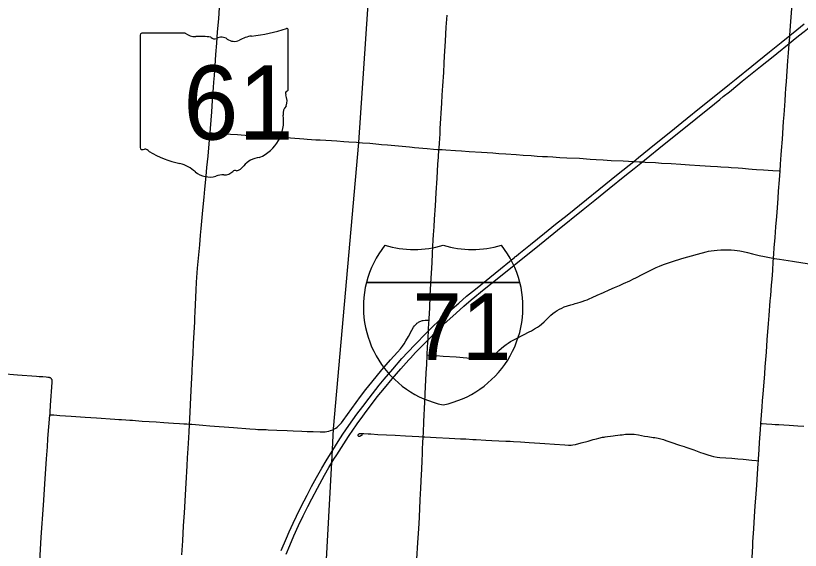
# Model space of a CAD drawing. Extents: x 9078 to 9739, y 4248 to 4966.
# Drawn here: x 9374.4 to 9448.2, y 4419.9 to 4470.1 of the extents above; entities that cross this region are included whole.
import ezdxf

# ---------------------------------------------------------------- set-up
doc = ezdxf.new("R2010")
doc.units = 0
for name, color, linetype in [('GM_X_County_Road', 7, 'Continuous'), ('GM_X_Interstate_Route', 7, 'Continuous'), ('GM_X_Interstate_Shield', 7, 'Continuous'), ('GM_X_State_Route', 7, 'Continuous'), ('GM_X_State_Shield', 7, 'Continuous'), ('GM_X_Township', 7, 'Continuous'), ('GM_X_Township_Road', 7, 'Continuous')]:
    doc.layers.add(name, color=color, linetype=linetype)

msp = doc.modelspace()

# ---------------------------------------------------------------- linework, layer by layer
at = {"layer": 'GM_X_County_Road'}
for points in [[(9446.815, 4462.765), (9446.846, 4463.245), (9446.893, 4463.899), (9446.967, 4464.88), (9447.035, 4465.861), (9447.094, 4466.597), (9447.155, 4467.414), (9447.16, 4467.488), (9447.203, 4468.076), (9447.214, 4468.229), (9447.278, 4469.132), (9447.369, 4470.358), (9447.496, 4471.993), (9447.569, 4472.974), (9447.574, 4473.033)], [(9414.23, 4457.523), (9414.239, 4457.66), (9414.267, 4458.106), (9414.329, 4459.006), (9414.358, 4459.498), (9414.495, 4461.873), (9414.545, 4462.61), (9414.602, 4463.511), (9414.675, 4464.739), (9414.726, 4465.641), (9414.76, 4466.296), (9414.843, 4467.688), (9414.918, 4468.998), (9414.99, 4470.144)], [(9446.305, 4455.497), (9446.352, 4456.128), (9446.414, 4457.027), (9446.44, 4457.436), (9446.514, 4458.5), (9446.632, 4460.136), (9446.675, 4460.79), (9446.771, 4462.099), (9446.815, 4462.765)], [(9413.296, 4441.491), (9413.306, 4441.652), (9413.359, 4442.626), (9413.418, 4443.774), (9413.481, 4444.921), (9413.535, 4445.904), (9413.589, 4446.887), (9413.635, 4447.789), (9413.693, 4449.018), (9413.723, 4449.509), (9413.768, 4450.246), (9413.813, 4450.983), (9413.89, 4452.212), (9413.969, 4453.44), (9414.054, 4454.832), (9414.095, 4455.487), (9414.138, 4456.142), (9414.182, 4456.796), (9414.23, 4457.523)], [(9445.685, 4447.299), (9445.715, 4447.72), (9445.759, 4448.279), (9445.831, 4449.26), (9445.906, 4450.241), (9445.982, 4451.222), (9446.048, 4452.04), (9446.111, 4452.939), (9446.158, 4453.594), (9446.242, 4454.656), (9446.305, 4455.497)], [(9444.5, 4431.771), (9444.611, 4433.337), (9444.657, 4433.909), (9444.71, 4434.563), (9444.774, 4435.298), (9444.857, 4436.442), (9444.905, 4437.096), (9445.012, 4438.486), (9445.093, 4439.631), (9445.217, 4441.184), (9445.277, 4441.919), (9445.383, 4443.309), (9445.421, 4443.799), (9445.501, 4444.779), (9445.547, 4445.351), (9445.611, 4446.167), (9445.66, 4446.972), (9445.685, 4447.299)], [(9413.282, 4441.228), (9413.296, 4441.491)], [(9413.166, 4438.988), (9413.167, 4439.015), (9413.201, 4439.652), (9413.212, 4439.867), (9413.241, 4440.471), (9413.248, 4440.614), (9413.282, 4441.228)], [(9413.127, 4438.224), (9413.166, 4438.988)], [(9413.033, 4436.461), (9413.038, 4436.564), (9413.08, 4437.301), (9413.127, 4438.224)], [(9412.744, 4430.538), (9412.763, 4430.909), (9412.817, 4431.975), (9412.906, 4433.777), (9412.971, 4435.253), (9413.033, 4436.461)], [(9376.701, 4418.834), (9376.733, 4419.375), (9376.839, 4421.094), (9377.038, 4424.121), (9377.194, 4426.575), (9377.33, 4428.454), (9377.416, 4429.596), (9377.466, 4430.332), (9377.522, 4431.109), (9377.582, 4431.803), (9377.632, 4432.605)], [(9444.26, 4428.272), (9444.271, 4428.432), (9444.335, 4429.331), (9444.378, 4429.986), (9444.404, 4430.394), (9444.459, 4431.21), (9444.495, 4431.701), (9444.5, 4431.771)], [(9411.971, 4416.635), (9411.978, 4416.733), (9411.997, 4416.986), (9412.071, 4417.968), (9412.146, 4419.032), (9412.251, 4420.588), (9412.332, 4421.898), (9412.398, 4422.962), (9412.443, 4423.864), (9412.469, 4424.52), (9412.508, 4425.257), (9412.524, 4425.584), (9412.565, 4426.485), (9412.585, 4426.895), (9412.615, 4427.551), (9412.642, 4428.206), (9412.676, 4429.025), (9412.692, 4429.434), (9412.711, 4429.926), (9412.744, 4430.538)], [(9443.387, 4414.774), (9443.427, 4415.343), (9443.462, 4415.916), (9443.514, 4416.734), (9443.588, 4417.88), (9443.632, 4418.534), (9443.668, 4419.188), (9443.725, 4420.252), (9443.749, 4420.661), (9443.828, 4421.888), (9443.904, 4423.033), (9443.966, 4424.016), (9444.05, 4425.161), (9444.102, 4425.979), (9444.178, 4427.042), (9444.242, 4428.024), (9444.26, 4428.272)]]:
    msp.add_lwpolyline(points, dxfattribs=at)
at = {"layer": 'GM_X_Interstate_Route'}
for points in [[(9399.408, 4419.86), (9399.885, 4420.994), (9400.146, 4421.595), (9400.518, 4422.417), (9400.834, 4423.084), (9401.27, 4423.966), (9401.829, 4425.061), (9402.251, 4425.858), (9402.724, 4426.721), (9403.212, 4427.575), (9403.632, 4428.28), (9404.189, 4429.188), (9404.249, 4429.282), (9404.758, 4430.09), (9405.208, 4430.775), (9405.765, 4431.586), (9406.523, 4432.656), (9407.059, 4433.382), (9407.656, 4434.165), (9408.621, 4435.388), (9409.088, 4435.958), (9409.884, 4436.897), (9410.75, 4437.882), (9411.303, 4438.487), (9411.981, 4439.2), (9413.019, 4440.25), (9413.241, 4440.471), (9413.717, 4440.943), (9414.434, 4441.616), (9415.043, 4442.166), (9416.09, 4443.087), (9416.835, 4443.729), (9417.657, 4444.409), (9421.353, 4447.404), (9421.401, 4447.475), (9421.481, 4447.506), (9421.738, 4447.71), (9422.824, 4448.586), (9424.167, 4449.664), (9425.187, 4450.49), (9426.276, 4451.361), (9431.068, 4455.219), (9432.538, 4456.401), (9432.984, 4456.762), (9434.005, 4457.588), (9436.365, 4459.495), (9437.069, 4460.06), (9437.579, 4460.473), (9438.726, 4461.403), (9439.947, 4462.371), (9441.547, 4463.654), (9442.184, 4464.171), (9443.654, 4465.354), (9445.315, 4466.691), (9446.4, 4467.568), (9447.214, 4468.229), (9447.864, 4468.757), (9448.568, 4469.322)], [(9445.654, 4466.272), (9446.003, 4466.551), (9447.16, 4467.488), (9447.533, 4467.79), (9448.043, 4468.203), (9448.553, 4468.615), (9448.874, 4468.87), (9449.127, 4469.073)], [(9414.704, 4441.116), (9415.842, 4442.156), (9416.579, 4442.809), (9417.266, 4443.395), (9418.471, 4444.384), (9420.644, 4446.132), (9422.111, 4447.317), (9423.326, 4448.294), (9425.369, 4449.941), (9427.797, 4451.895), (9428.883, 4452.769), (9430.225, 4453.848), (9431.694, 4455.031), (9432.591, 4455.747), (9433.35, 4456.356), (9433.55, 4456.517), (9435.404, 4458.008), (9436.62, 4458.982), (9440.13, 4461.816), (9440.64, 4462.228), (9440.959, 4462.485), (9441.534, 4462.947), (9441.726, 4463.101), (9442.747, 4463.925), (9444.466, 4465.321), (9445.654, 4466.272)], [(9411.55, 4437.925), (9412.02, 4438.439), (9412.7, 4439.152), (9413.201, 4439.652), (9414.035, 4440.485), (9414.631, 4441.049), (9414.704, 4441.116)], [(9399.853, 4419.493), (9400.2, 4420.326), (9400.59, 4421.23), (9401.03, 4422.201), (9401.449, 4423.092), (9401.888, 4423.974), (9402.264, 4424.703), (9402.807, 4425.715), (9403.482, 4426.936), (9403.891, 4427.647), (9404.17, 4428.108), (9404.359, 4428.419), (9404.618, 4428.837), (9404.839, 4429.183), (9405.059, 4429.529), (9405.508, 4430.216), (9405.735, 4430.557), (9406.195, 4431.237), (9406.428, 4431.574), (9406.618, 4431.842), (9406.81, 4432.108), (9407.488, 4433.035), (9407.784, 4433.428), (9408.435, 4434.273), (9409.106, 4435.102), (9409.841, 4435.986), (9410.644, 4436.918), (9411.411, 4437.773), (9411.55, 4437.925)]]:
    msp.add_lwpolyline(points, dxfattribs=at)
at = {"layer": 'GM_X_Interstate_Shield'}
for p, q in [((9407.412, 4445.017), (9421.839, 4445.017)), ((9421.839, 4445.017), (9407.412, 4445.017)), ((9421.839, 4445.017), (9407.412, 4445.017))]:
    msp.add_line(p, q, dxfattribs=at)
for centre, start, end in [((9416.501, 4442.718), 141.66896, 165.80665), ((9411.886, 4457.499), 253.00908, 286.99093), ((9417.365, 4457.499), 253.00908, 286.99093), ((9412.751, 4442.718), 14.19335, 38.33104), ((9416.501, 4442.718), 165.80665, 258.46304), ((9412.751, 4442.718), 281.53696, 14.19335)]:
    msp.add_arc(centre, 9.375, start, end, dxfattribs=at)
at = {"layer": 'GM_X_State_Route'}
msp.add_lwpolyline([(9390.069, 4419.454), (9390.146, 4420.764), (9390.22, 4422.155), (9390.294, 4423.382), (9390.457, 4426.165), (9390.553, 4427.802), (9390.597, 4428.538), (9390.654, 4429.436), (9390.71, 4430.417), (9390.741, 4430.99), (9390.776, 4431.644), (9390.782, 4431.721), (9390.811, 4432.217), (9390.876, 4433.526), (9390.913, 4434.26), (9390.97, 4435.482), (9391.026, 4436.619), (9391.072, 4437.52), (9391.115, 4438.338), (9391.159, 4439.321), (9391.269, 4441.285), (9391.286, 4441.695), (9391.316, 4442.268), (9391.405, 4444.315), (9391.448, 4445.051), (9391.535, 4446.359), (9391.592, 4447.012), (9391.749, 4448.561), (9391.826, 4449.46), (9391.886, 4450.112), (9392.042, 4451.827), (9392.161, 4453.05), (9392.232, 4453.785), (9392.343, 4455.009), (9392.421, 4455.825), (9392.521, 4456.886), (9392.655, 4458.438), (9392.713, 4459.083), (9392.75, 4459.499), (9392.87, 4461.052), (9392.954, 4462.114), (9393.043, 4463.341), (9393.076, 4463.831), (9393.125, 4464.485), (9393.191, 4465.384), (9393.268, 4466.447), (9393.35, 4467.51), (9393.425, 4468.572), (9393.522, 4469.796), (9393.601, 4470.859)], dxfattribs=at)
at = {"layer": 'GM_X_State_Shield'}
for p, q in [((9400.067, 4463.192), (9400.067, 4468.72)), ((9386.145, 4468.276), (9386.145, 4457.71)), ((9390.359, 4468.458), (9386.282, 4468.458)), ((9400.065, 4463.194), (9400.067, 4463.192))]:
    msp.add_line(p, q, dxfattribs=at)
for centre, radius, start, end in [((9395.108, 4482.864), 14.764, 275.84447, 288.90645), ((9399.912, 4468.743), 0.155, 351.86209, 97.738), ((9386.305, 4468.299), 0.161, 98.1301, 188.1301), ((9391.33, 4469.685), 1.564, 231.61951, 271.11188), ((9391.849, 4462.526), 5.616, 80.48669, 94.98827), ((9393.124, 4468.354), 0.451, 219.79206, 297.10237), ((9393.786, 4467.132), 0.938, 54.46668, 119.14113), ((9394.997, 4468.807), 1.129, 233.85621, 294.82819), ((9396.991, 4465.231), 2.97, 97.34618, 120.76885), ((9400.031, 4462.787), 0.24, 107.94398, 210.33697), ((9399.901, 4463.171), 0.166, 289.60381, 7.73413), ((9398.505, 4462.088), 1.44, 340.03296, 23.64957), ((9400.622, 4460.879), 1.048, 136.8065, 186.92959), ((9395.935, 4460.176), 3.693, 292.30889, 8.98584), ((9386.306, 4457.687), 0.163, 171.95839, 258.30661), ((9386.331, 4458.768), 1.242, 267.33899, 280.60386), ((9386.585, 4457.1), 0.448, 29.74838, 93.27175), ((9392.238, 4466.594), 10.661, 240.41292, 257.1985), ((9389.059, 4452.963), 3.336, 47.18416, 75.83597), ((9397.492, 4454.743), 2.022, 94.40312, 142.57675), ((9392.667, 4457.048), 2.117, 230.70037, 286.29184), ((9394.045, 4456.257), 1.128, 268.77702, 315.54927), ((9395.065, 4455.233), 0.318, 65.75173, 132.64842), ((9394.929, 4456.686), 1.193, 282.87319, 323.27711), ((9393.89, 4453.395), 1.739, 85.69512, 111.20995)]:
    msp.add_arc(centre, radius, start, end, dxfattribs=at)
at = {"layer": 'GM_X_Township'}
msp.add_lwpolyline([(9403.572, 4417.317), (9404.179, 4428.722), (9404.315, 4431.281), (9406.691, 4458.18), (9408.516, 4485.114), (9409.016, 4501.409), (9409.03, 4501.874), (9409.589, 4519.144), (9409.927, 4527.297), (9410.369, 4541.158), (9410.412, 4544.235), (9411.301, 4562.535), (9438.791, 4566.274), (9441.547, 4566.662)], dxfattribs=at)
at = {"layer": 'GM_X_Township_Road'}
for points in [[(9392.713, 4459.083), (9392.923, 4459.071), (9393.332, 4459.047), (9393.987, 4459.003), (9395.296, 4458.925), (9396.36, 4458.849), (9397.015, 4458.809), (9397.67, 4458.77), (9398.652, 4458.707), (9399.552, 4458.651), (9400.288, 4458.601), (9401.514, 4458.52), (9401.841, 4458.494), (9402.66, 4458.443), (9403.068, 4458.419), (9404.132, 4458.352), (9404.623, 4458.323), (9405.277, 4458.276), (9405.769, 4458.246)], [(9405.769, 4458.246), (9406.487, 4458.196), (9407.035, 4458.161), (9407.722, 4458.107), (9408.588, 4458.026), (9408.832, 4457.998), (9409.404, 4457.949), (9410.423, 4457.868), (9411.445, 4457.782), (9411.711, 4457.746), (9411.932, 4457.72), (9413.116, 4457.621), (9413.705, 4457.566), (9414.078, 4457.53), (9414.23, 4457.523)], [(9414.23, 4457.523), (9414.546, 4457.507), (9414.873, 4457.484), (9415.772, 4457.414), (9416.345, 4457.382), (9417.081, 4457.34), (9418.227, 4457.275), (9419.291, 4457.201), (9419.863, 4457.154), (9420.517, 4457.108), (9421.5, 4457.043), (9422.155, 4456.997), (9422.891, 4456.943), (9423.463, 4456.904), (9423.953, 4456.875), (9424.441, 4456.849), (9424.93, 4456.819), (9425.256, 4456.801), (9425.584, 4456.783), (9426.239, 4456.745), (9427.437, 4456.692), (9428.449, 4456.621), (9429.023, 4456.592), (9429.678, 4456.552), (9430.414, 4456.502), (9431.563, 4456.459), (9432.538, 4456.401), (9433.037, 4456.375), (9433.35, 4456.356), (9433.611, 4456.341), (9434.593, 4456.287), (9435.166, 4456.249), (9436.067, 4456.191), (9436.967, 4456.142), (9437.784, 4456.086), (9438.766, 4456.017), (9439.767, 4455.959), (9440.403, 4455.919), (9440.73, 4455.905), (9441.466, 4455.86), (9441.71, 4455.836), (9442.365, 4455.796), (9442.773, 4455.766), (9443.341, 4455.709), (9443.666, 4455.684), (9444.074, 4455.655), (9444.729, 4455.619), (9445.628, 4455.551), (9446.201, 4455.505), (9446.305, 4455.497)], [(9413.127, 4438.224), (9413.165, 4438.221), (9413.489, 4438.195), (9413.98, 4438.156), (9414.633, 4438.11), (9415.859, 4438.028), (9416.84, 4437.96), (9417.312, 4437.925), (9417.823, 4437.872), (9418.233, 4437.846), (9418.477, 4437.848), (9418.721, 4437.87), (9418.882, 4437.902), (9418.96, 4437.925), (9419.037, 4437.955), (9419.111, 4437.989), (9419.182, 4438.029), (9419.252, 4438.072), (9419.383, 4438.17), (9419.507, 4438.278), (9419.859, 4438.622), (9420.098, 4438.846), (9420.286, 4439.005), (9420.547, 4439.203), (9420.751, 4439.341), (9420.961, 4439.468), (9421.393, 4439.703), (9422.191, 4440.123), (9422.698, 4440.385), (9422.915, 4440.499), (9423.202, 4440.657), (9423.482, 4440.827), (9423.685, 4440.965), (9423.878, 4441.116), (9424.122, 4441.335), (9424.412, 4441.623), (9424.763, 4441.966), (9424.948, 4442.127), (9425.145, 4442.273), (9425.353, 4442.404), (9425.568, 4442.521), (9425.788, 4442.629), (9426.015, 4442.724), (9426.324, 4442.833), (9426.639, 4442.929), (9426.884, 4442.993), (9427.042, 4443.039), (9427.271, 4443.101), (9427.494, 4443.176), (9427.687, 4443.245), (9427.949, 4443.334), (9428.161, 4443.408), (9428.35, 4443.481), (9428.649, 4443.616), (9429.096, 4443.826), (9429.692, 4444.096), (9430.218, 4444.325), (9430.743, 4444.557), (9431.193, 4444.754), (9431.567, 4444.921), (9432.161, 4445.191), (9432.532, 4445.36), (9432.752, 4445.466), (9433.412, 4445.794), (9433.85, 4446.018), (9434.656, 4446.421), (9434.954, 4446.557), (9435.333, 4446.713), (9435.718, 4446.854), (9436.184, 4447.011), (9437.049, 4447.265), (9438.546, 4447.695), (9439.337, 4447.911), (9439.576, 4447.968), (9439.819, 4448.005), (9440.39, 4448.065), (9440.717, 4448.088), (9441.127, 4448.107), (9441.454, 4448.109), (9441.7, 4448.1), (9442.026, 4448.073), (9442.269, 4448.039), (9442.51, 4447.995), (9442.831, 4447.925), (9443.23, 4447.832), (9443.707, 4447.718), (9444.343, 4447.567), (9444.821, 4447.459), (9445.142, 4447.392), (9445.474, 4447.33), (9445.685, 4447.299)], [(9445.685, 4447.299), (9445.757, 4447.287), (9446.241, 4447.203), (9447.455, 4447.02), (9448.427, 4446.876), (9449.478, 4446.711), (9450.103, 4446.619), (9450.692, 4446.53), (9451.42, 4446.418), (9452.15, 4446.321), (9452.958, 4446.188), (9453.929, 4446.04), (9454.417, 4445.986), (9454.907, 4445.949), (9455.397, 4445.922), (9455.806, 4445.914), (9456.131, 4445.921), (9456.619, 4445.947), (9457.437, 4445.985), (9458.746, 4446.048), (9459.563, 4446.098), (9460.951, 4446.206), (9461.604, 4446.265), (9461.974, 4446.301)], [(9404.327, 4431.235), (9404.399, 4431.27), (9404.541, 4431.353), (9404.674, 4431.448), (9404.799, 4431.555), (9404.916, 4431.671), (9405.078, 4431.857), (9405.228, 4432.052), (9406.037, 4433.191), (9406.868, 4434.314), (9407.366, 4434.968), (9407.932, 4435.673), (9408.875, 4436.813), (9409.682, 4437.745), (9410.342, 4438.477), (9410.609, 4438.79), (9410.809, 4439.051), (9410.948, 4439.254), (9411.12, 4439.533), (9411.361, 4439.964), (9411.68, 4440.538), (9411.848, 4440.82), (9411.94, 4440.956), (9412.045, 4441.082), (9412.104, 4441.14), (9412.165, 4441.194), (9412.231, 4441.244), (9412.299, 4441.289), (9412.37, 4441.33), (9412.444, 4441.366), (9412.52, 4441.397), (9412.598, 4441.423), (9412.678, 4441.444), (9412.758, 4441.46), (9412.921, 4441.479), (9413.086, 4441.485), (9413.296, 4441.491)], [(9373.128, 4436.465), (9374.601, 4436.353), (9376.402, 4436.211), (9376.649, 4436.198), (9376.73, 4436.191), (9376.976, 4436.18), (9377.304, 4436.159), (9377.446, 4436.144), (9377.549, 4436.131), (9377.587, 4436.123), (9377.628, 4436.109), (9377.665, 4436.091), (9377.7, 4436.072), (9377.732, 4436.046), (9377.762, 4436.018), (9377.787, 4435.984), (9377.809, 4435.95), (9377.825, 4435.91), (9377.837, 4435.871), (9377.841, 4435.833), (9377.844, 4435.792), (9377.842, 4435.628), (9377.69, 4433.498), (9377.645, 4432.843), (9377.632, 4432.605)], [(9377.632, 4432.605), (9378.022, 4432.579), (9378.594, 4432.543), (9379.656, 4432.472), (9380.964, 4432.388), (9382.026, 4432.316), (9383.743, 4432.186), (9384.125, 4432.165), (9384.249, 4432.156), (9384.304, 4432.151), (9384.334, 4432.149), (9384.361, 4432.147), (9384.395, 4432.144), (9384.78, 4432.119), (9385.174, 4432.093), (9385.414, 4432.078), (9385.686, 4432.06), (9386.339, 4432.011), (9387.645, 4431.92), (9388.38, 4431.866), (9388.788, 4431.842), (9389.279, 4431.815), (9389.851, 4431.777), (9390.24, 4431.754), (9390.514, 4431.737), (9390.782, 4431.721)], [(9444.5, 4431.771), (9444.618, 4431.764), (9445.027, 4431.74), (9445.518, 4431.712), (9445.845, 4431.695), (9446.172, 4431.678), (9446.66, 4431.65), (9447.147, 4431.619), (9447.555, 4431.592), (9447.963, 4431.568), (9448.536, 4431.534)], [(9390.782, 4431.721), (9390.984, 4431.709), (9392.043, 4431.613), (9392.696, 4431.558), (9394.901, 4431.393), (9396.452, 4431.27), (9396.968, 4431.239), (9397.212, 4431.224), (9397.481, 4431.216), (9397.702, 4431.208), (9397.916, 4431.202), (9397.997, 4431.201), (9398.16, 4431.187), (9398.977, 4431.148), (9399.959, 4431.112), (9400.532, 4431.093), (9401.349, 4431.056), (9401.84, 4431.037), (9402.147, 4431.027)], [(9402.147, 4431.027), (9402.41, 4431.019), (9403.064, 4430.994), (9403.301, 4430.995), (9403.459, 4430.994), (9403.542, 4430.999), (9403.704, 4431.024), (9403.864, 4431.061), (9404.021, 4431.109), (9404.251, 4431.198), (9404.327, 4431.235)], [(9407.028, 4430.726), (9406.945, 4430.661), (9406.897, 4430.626), (9406.869, 4430.607), (9406.827, 4430.582), (9406.807, 4430.573), (9406.784, 4430.566), (9406.766, 4430.563), (9406.748, 4430.561), (9406.729, 4430.561), (9406.707, 4430.565), (9406.687, 4430.572), (9406.67, 4430.581), (9406.655, 4430.59), (9406.642, 4430.605), (9406.63, 4430.624), (9406.624, 4430.643), (9406.622, 4430.658), (9406.622, 4430.67), (9406.625, 4430.69), (9406.629, 4430.708), (9406.635, 4430.722), (9406.656, 4430.756), (9406.67, 4430.771), (9406.688, 4430.789), (9406.702, 4430.799), (9406.723, 4430.812), (9406.754, 4430.826), (9406.796, 4430.838), (9406.835, 4430.845), (9406.871, 4430.848), (9406.917, 4430.849), (9406.999, 4430.847), (9407.162, 4430.833), (9407.572, 4430.806), (9407.817, 4430.796), (9408.472, 4430.757), (9410.111, 4430.676), (9411.095, 4430.629), (9412.323, 4430.554), (9412.744, 4430.538)], [(9412.744, 4430.538), (9412.897, 4430.532), (9413.962, 4430.474), (9415.191, 4430.413), (9416.255, 4430.353), (9416.747, 4430.323), (9417.402, 4430.29), (9417.73, 4430.275), (9418.631, 4430.228), (9419.203, 4430.195), (9420.515, 4430.13), (9420.924, 4430.105), (9421.251, 4430.085), (9421.906, 4430.046), (9422.72, 4429.99), (9423.701, 4429.938), (9424.192, 4429.904), (9425.093, 4429.843), (9426.075, 4429.772), (9426.403, 4429.754), (9426.649, 4429.756), (9426.812, 4429.772), (9427.054, 4429.816), (9427.611, 4429.954), (9428.247, 4430.121), (9428.719, 4430.261), (9429.034, 4430.353), (9429.272, 4430.415), (9429.592, 4430.482), (9429.752, 4430.508), (9429.85, 4430.521), (9430.072, 4430.549), (9430.37, 4430.587), (9430.606, 4430.617), (9430.809, 4430.643), (9431.04, 4430.672), (9431.273, 4430.701), (9431.46, 4430.725), (9431.771, 4430.765), (9432.015, 4430.785), (9432.179, 4430.79), (9432.343, 4430.785), (9432.588, 4430.764), (9432.994, 4430.711), (9433.558, 4430.599), (9433.881, 4430.545), (9434.367, 4430.474), (9434.53, 4430.453), (9434.691, 4430.429), (9434.851, 4430.395), (9435.09, 4430.334), (9435.326, 4430.264), (9435.549, 4430.193), (9436.038, 4430.023), (9436.323, 4429.927), (9436.575, 4429.843), (9436.833, 4429.756), (9437.07, 4429.677), (9437.285, 4429.605), (9437.454, 4429.548), (9437.806, 4429.43), (9438.192, 4429.296), (9438.805, 4429.07), (9439.036, 4428.988), (9439.501, 4428.827), (9439.815, 4428.734), (9440.054, 4428.68), (9440.377, 4428.623), (9440.621, 4428.591), (9441.768, 4428.518), (9442.34, 4428.468), (9442.83, 4428.419), (9443.645, 4428.33), (9444.053, 4428.292), (9444.26, 4428.272)]]:
    msp.add_lwpolyline(points, dxfattribs=at)

# ---------------------------------------------------------------- texts
at = {"layer": 'GM_X_Interstate_Shield'}
msp.add_text('71', height=6.25, dxfattribs=at).set_placement((9411.738, 4437.752))
at = {"layer": 'GM_X_State_Shield'}
msp.add_text('61', height=6.961, dxfattribs=at).set_placement((9390.196, 4458.455))

doc.saveas('drawing.dxf')
